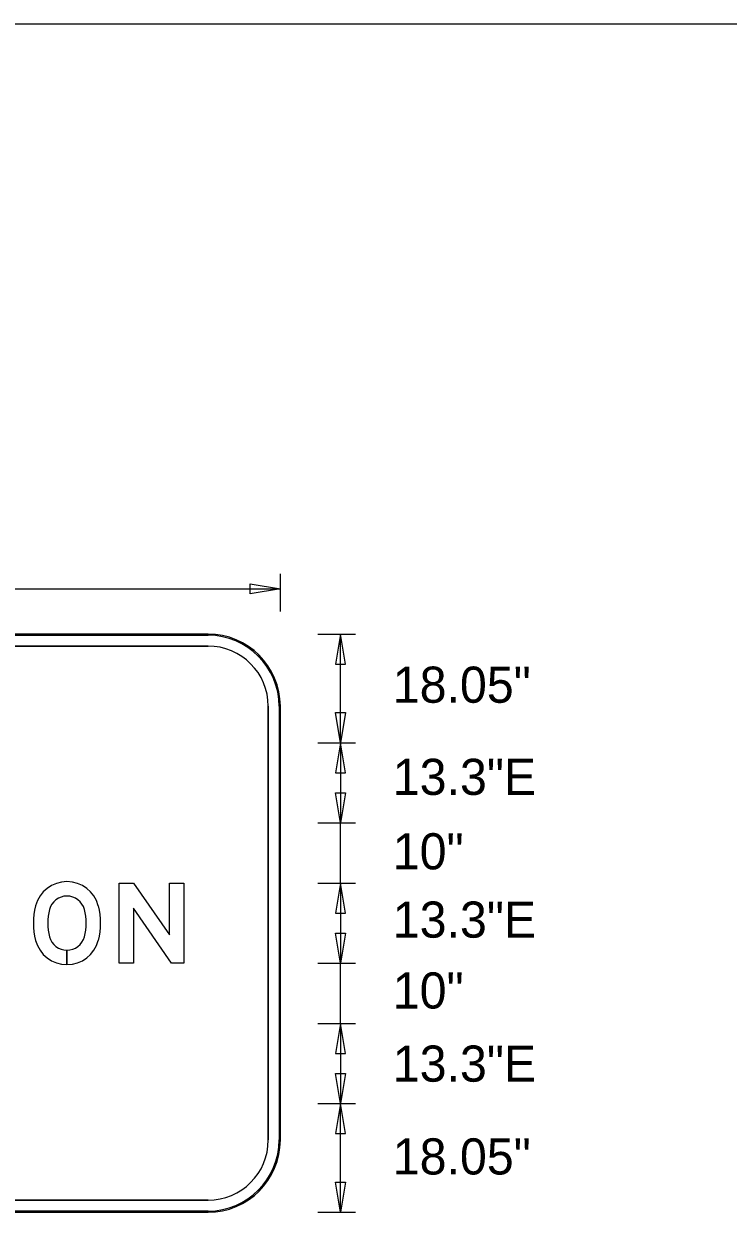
# Model space of a CAD drawing. Extents: x 122633 to 124574, y -23288 to -22025.
# Drawn here: x 124224.8 to 124341.8, y -22804.9 to -22607.5 of the extents above; entities that cross this region are included whole.
import ezdxf

# ---------------------------------------------------------------- set-up
doc = ezdxf.new("R2010")
doc.units = 0
for name, color, linetype in [('GSBWFill', 7, 'Continuous'), ('GSColorFill', 7, 'Continuous'), ('GSDims', 7, 'Continuous'), ('GSOutline', 7, 'Continuous'), ('SheetLinesMisc2_dp', 7, 'Continuous')]:
    doc.layers.add(name, color=color, linetype=linetype)

msp = doc.modelspace()

# ---------------------------------------------------------------- linework, layer by layer
at = {"layer": 'GSBWFill'}
for p, q in [((124255.44, -22708.87), (124123.44, -22708.87)), ((124123.44, -22710.87), (124255.44, -22710.87)), ((124265.44, -22720.87), (124265.44, -22792.87)), ((124267.44, -22792.87), (124267.44, -22720.87)), ((124232, -22763.75), (124232, -22761.35)), ((124232, -22761.35), (124232, -22763.75)), ((124255.44, -22802.87), (124123.46, -22802.87)), ((124123.46, -22804.87), (124255.44, -22804.87))]:
    msp.add_line(p, q, dxfattribs=at)
msp.add_lwpolyline([(124251.42, -22750.22), (124251.42, -22763.52), (124249.36, -22763.52), (124243.04, -22754.4), (124243.04, -22763.52), (124240.65, -22763.52), (124240.65, -22750.22), (124243.05, -22750.22), (124249.03, -22758.83), (124249.03, -22750.22)], close=True, dxfattribs=at)
for centre, radius, start, end in [((124255.44, -22720.87), 12, 0, 90), ((124255.44, -22720.87), 10, 0, 90), ((124255.44, -22792.87), 12, 270, 0), ((124255.44, -22792.87), 10, 270, 0)]:
    msp.add_arc(centre, radius, start, end, dxfattribs=at)
for centre, major_axis, start_param, end_param in [((124232, -22755.37), (0, 5.39), 4.973521, 7.592849), ((124232, -22755.37), (0, 3), 4.973521, 7.592849), ((124237.59, -22756.87), (0, 11.17), 1.309664, 1.831929), ((124226.42, -22756.87), (0, 11.17), 4.451257, 4.973521), ((124237.59, -22756.87), (0, 8.78), 1.309664, 1.831929), ((124226.42, -22756.87), (0, 8.78), 4.451257, 4.973521), ((124232, -22758.36), (0, 5.39), 1.831929, 3.141593), ((124232, -22758.36), (0, 3), 1.831929, 3.141593), ((124232, -22758.36), (0, 3), 3.141815, 4.451257), ((124232, -22758.36), (0, 5.39), 3.141716, 4.451257)]:
    msp.add_ellipse(centre, major_axis=major_axis, ratio=0.999998, start_param=start_param, end_param=end_param, dxfattribs=at)
at = {"layer": 'GSColorFill'}
for p, q in [((124255.44, -22708.87), (124123.44, -22708.87)), ((124255.44, -22708.87), (124123.44, -22708.87)), ((124255.44, -22708.87), (124123.44, -22708.87)), ((124123.44, -22709.07), (124255.44, -22709.07)), ((124123.44, -22710.87), (124255.44, -22710.87)), ((124265.44, -22720.87), (124265.44, -22792.87)), ((124267.24, -22720.87), (124267.24, -22792.87)), ((124267.44, -22792.87), (124267.44, -22720.87)), ((124267.44, -22792.87), (124267.44, -22720.87)), ((124267.44, -22792.87), (124267.44, -22720.87)), ((124232, -22763.75), (124232, -22761.35)), ((124232, -22761.35), (124232, -22763.75)), ((124255.44, -22802.87), (124123.46, -22802.87)), ((124255.44, -22804.67), (124123.44, -22804.67)), ((124123.44, -22804.87), (124255.44, -22804.87)), ((124123.44, -22804.87), (124255.44, -22804.87)), ((124123.46, -22804.87), (124255.44, -22804.87))]:
    msp.add_line(p, q, dxfattribs=at)
msp.add_lwpolyline([(124251.42, -22750.22), (124251.42, -22763.52), (124249.36, -22763.52), (124243.04, -22754.4), (124243.04, -22763.52), (124240.65, -22763.52), (124240.65, -22750.22), (124243.05, -22750.22), (124249.03, -22758.83), (124249.03, -22750.22)], close=True, dxfattribs=at)
for centre, radius, start, end in [((124255.44, -22720.87), 12, 0, 90), ((124255.44, -22720.87), 12, 0, 90), ((124255.44, -22720.87), 12, 0, 90), ((124255.44, -22720.87), 11.8, 0, 90), ((124255.44, -22720.87), 10, 0, 90), ((124255.44, -22792.87), 12, 270, 0), ((124255.44, -22792.87), 12, 270, 0), ((124255.44, -22792.87), 10, 270, 0), ((124255.44, -22792.87), 12, 270, 0), ((124255.44, -22792.87), 11.8, 270, 0)]:
    msp.add_arc(centre, radius, start, end, dxfattribs=at)
for centre, major_axis, start_param, end_param in [((124232, -22755.37), (0, 5.39), 4.973521, 7.592849), ((124232, -22755.37), (0, 3), 4.973521, 7.592849), ((124237.59, -22756.87), (0, 11.17), 1.309664, 1.831929), ((124226.42, -22756.87), (0, 11.17), 4.451257, 4.973521), ((124237.59, -22756.87), (0, 8.78), 1.309664, 1.831929), ((124226.42, -22756.87), (0, 8.78), 4.451257, 4.973521), ((124232, -22758.36), (0, 5.39), 1.831929, 3.141593), ((124232, -22758.36), (0, 3), 1.831929, 3.141593), ((124232, -22758.36), (0, 3), 3.141815, 4.451257), ((124232, -22758.36), (0, 5.39), 3.141716, 4.451257)]:
    msp.add_ellipse(centre, major_axis=major_axis, ratio=0.999998, start_param=start_param, end_param=end_param, dxfattribs=at)
at = {"layer": 'GSDims'}
for p, q in [((124267.44, -22705.12), (124267.44, -22698.87)), ((124111.44, -22701.37), (124267.44, -22701.37)), ((124267.44, -22705.12), (124267.44, -22705.12)), ((124273.69, -22708.87), (124279.94, -22708.87)), ((124273.69, -22708.87), (124273.69, -22708.87)), ((124277.44, -22726.92), (124277.44, -22708.87)), ((124273.69, -22726.92), (124279.94, -22726.92)), ((124273.69, -22726.92), (124279.94, -22726.92)), ((124277.44, -22726.92), (124277.44, -22740.22)), ((124273.69, -22740.22), (124279.94, -22740.22)), ((124273.69, -22740.22), (124279.94, -22740.22)), ((124277.44, -22750.22), (124277.44, -22740.22)), ((124273.69, -22750.22), (124279.94, -22750.22)), ((124273.69, -22750.22), (124279.94, -22750.22)), ((124277.44, -22750.22), (124277.44, -22763.52)), ((124273.69, -22763.52), (124279.94, -22763.52)), ((124273.69, -22763.52), (124279.94, -22763.52)), ((124277.44, -22773.52), (124277.44, -22763.52)), ((124273.69, -22773.52), (124279.94, -22773.52)), ((124273.69, -22773.52), (124279.94, -22773.52)), ((124277.44, -22773.52), (124277.44, -22786.82)), ((124273.69, -22786.82), (124279.94, -22786.82)), ((124273.69, -22786.82), (124279.94, -22786.82)), ((124277.44, -22804.87), (124277.44, -22786.82)), ((124273.69, -22804.87), (124279.94, -22804.87)), ((124273.69, -22804.87), (124273.69, -22804.87))]:
    msp.add_line(p, q, dxfattribs=at)
for points in [[(124267.44, -22701.37), (124262.44, -22702.2), (124262.44, -22700.53)], [(124277.44, -22708.87), (124276.61, -22713.87), (124278.27, -22713.87)], [(124277.44, -22726.92), (124276.61, -22721.92), (124278.27, -22721.92)], [(124277.44, -22726.92), (124276.61, -22731.92), (124278.27, -22731.92)], [(124277.44, -22740.22), (124276.61, -22735.22), (124278.27, -22735.22)], [(124277.44, -22750.22), (124276.61, -22755.22), (124278.27, -22755.22)], [(124277.44, -22763.52), (124276.61, -22758.52), (124278.27, -22758.52)], [(124277.44, -22773.52), (124276.61, -22778.52), (124278.27, -22778.52)], [(124277.44, -22786.82), (124276.61, -22781.82), (124278.27, -22781.82)], [(124277.44, -22786.82), (124276.61, -22791.82), (124278.27, -22791.82)], [(124277.44, -22804.87), (124276.61, -22799.87), (124278.27, -22799.87)]]:
    msp.add_lwpolyline(points, close=True, dxfattribs=at)
at = {"layer": 'GSOutline'}
for p, q in [((124255.44, -22708.87), (124123.44, -22708.87)), ((124255.44, -22710.87), (124123.44, -22710.87)), ((124265.44, -22792.87), (124265.44, -22720.87)), ((124267.44, -22792.87), (124267.44, -22720.87)), ((124123.44, -22802.87), (124255.44, -22802.87)), ((124123.44, -22804.87), (124255.44, -22804.87))]:
    msp.add_line(p, q, dxfattribs=at)
msp.add_lwpolyline([(124251.42, -22750.22), (124251.42, -22763.52), (124249.36, -22763.52), (124243.04, -22754.4), (124243.04, -22763.52), (124240.65, -22763.52), (124240.65, -22750.22), (124243.05, -22750.22), (124249.03, -22758.83), (124249.03, -22750.22)], close=True, dxfattribs=at)
for centre, radius, start, end in [((124255.44, -22720.87), 12, 0, 90), ((124255.44, -22720.87), 10, 0, 90), ((124255.44, -22792.87), 12, 270, 0), ((124255.44, -22792.87), 10, 270, 0)]:
    msp.add_arc(centre, radius, start, end, dxfattribs=at)
for centre, major_axis, start_param, end_param in [((124232, -22755.37), (0, 5.39), 4.973521, 7.592849), ((124232, -22755.37), (0, 3), 4.973521, 7.592849), ((124237.59, -22756.87), (0, 11.17), 1.309664, 1.831929), ((124226.42, -22756.87), (0, 11.17), 4.451257, 4.973521), ((124237.59, -22756.87), (0, 8.78), 1.309664, 1.831929), ((124226.42, -22756.87), (0, 8.78), 4.451257, 4.973521), ((124232, -22758.36), (0, 5.39), 1.831929, 4.451257), ((124232, -22758.36), (0, 3), 1.831929, 4.451257)]:
    msp.add_ellipse(centre, major_axis=major_axis, ratio=0.999998, start_param=start_param, end_param=end_param, dxfattribs=at)
at = {"layer": 'SheetLinesMisc2_dp'}
msp.add_line((123883.65, -22607.55), (124497.63, -22607.55), dxfattribs=at)

# ---------------------------------------------------------------- texts
at = {"layer": 'GSDims'}
for s, p in [('18.05"', (124286.12, -22720.28)), ('13.3"E', (124286.12, -22735.58)), ('10"', (124286.12, -22747.94)), ('13.3"E', (124286.12, -22759.28)), ('10"', (124286.12, -22771.05)), ('13.3"E', (124286.12, -22783.19)), ('18.05"', (124286.12, -22798.6))]:
    msp.add_text(s, height=6, dxfattribs=at).set_placement(p)

doc.saveas('drawing.dxf')
